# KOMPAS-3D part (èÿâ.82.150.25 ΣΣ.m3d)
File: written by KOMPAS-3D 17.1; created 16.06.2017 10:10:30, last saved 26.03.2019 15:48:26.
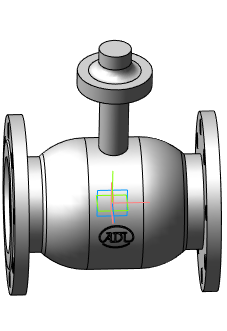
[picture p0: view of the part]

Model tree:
1. Операция без истории:3  (labels: Сталь 20  ГОСТ 1050-88)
